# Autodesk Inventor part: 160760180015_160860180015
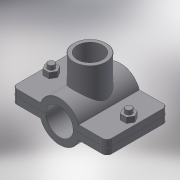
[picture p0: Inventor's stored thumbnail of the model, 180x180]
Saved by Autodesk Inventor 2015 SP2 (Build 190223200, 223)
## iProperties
Created: 2017-05
Part Number: 160760180015_160860180015
Material: Generic
Description: PLASSON SADDLE 180-1.1/2"
Document SubType Name: Modeling
Designer: KIM
Density: 1 g/cm^3
Appearance: Default
Author: KIM
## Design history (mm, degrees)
derived "16076.ipt"
feature "Solid1::16076.ipt"
feature "Solid2::16076.ipt"
tag "TaggingFeature1"
body "Solid1"
other parameters: "d0" = 198, "d1" = 245, "d4" = 154, "d5" = 0, "d6" = 12.25, "d7" = 245, "d8" = 0.1, "d10" = 0, "d11" = 1.8, "d14" = 58.2985, "d20" = 1.8, "d23" = 1.8, "d36" = 15, "d37" = 12, "d38" = 98, "d39" = 0, "d40" = 3, "d41" = 5, "d42" = 0, "d44" = 3, "d45" = 0, "d46" = 1.8, "d51" = 128, "d52" = 44.845, "d53" = 25, "d54" = 0, "d57" = 0, "d58" = 194.4, "d60" = 0, "d62" = 15, "d63" = 12, "G_" = 44.845, "A_" = 128, "L_" = 245, "L_1" = 154, "l_2" = 25
